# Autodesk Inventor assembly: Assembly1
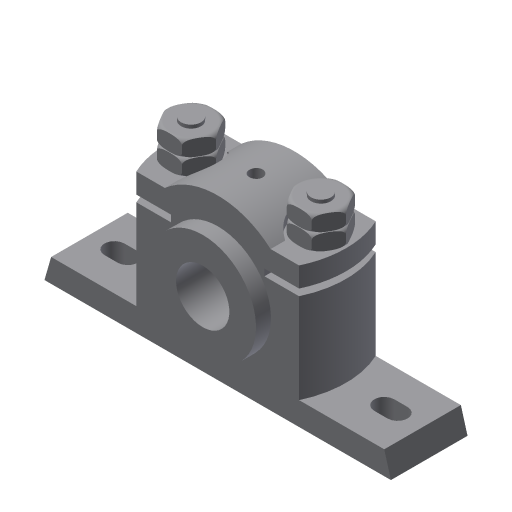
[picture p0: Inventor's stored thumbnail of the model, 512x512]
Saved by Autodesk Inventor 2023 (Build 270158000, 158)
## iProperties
Created: 2016-03
Part Number: Assembly1
Document SubType Name: Assembly
Designer: Sandeep
Author: Sandeep
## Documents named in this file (7)
- D:\PROJECTS\Project 2022\Autodesk Inventor For Professional 2023\RESOURCES INVENTOR 2023\RESOURCES INVENTOR 2023\Inventor_2023_Part\Inventor_2023_Part\c13_Inv_2023_prt\fig-13-7\Plummer block assy\Assembly1.iam
- D:\PROJECTS\Project 2022\Autodesk Inventor For Professional 2023\RESOURCES INVENTOR 2023\RESOURCES INVENTOR 2023\Inventor_2023_Part\Inventor_2023_Part\c13_Inv_2023_prt\fig-13-7\Plummer block assy\Casting.ipt
- D:\PROJECTS\Project 2022\Autodesk Inventor For Professional 2023\RESOURCES INVENTOR 2023\RESOURCES INVENTOR 2023\Inventor_2023_Part\Inventor_2023_Part\c13_Inv_2023_prt\fig-13-7\Plummer block assy\Brasses.ipt
- D:\PROJECTS\Project 2022\Autodesk Inventor For Professional 2023\RESOURCES INVENTOR 2023\RESOURCES INVENTOR 2023\Inventor_2023_Part\Inventor_2023_Part\c13_Inv_2023_prt\fig-13-7\Plummer block assy\Cap.ipt
- D:\PROJECTS\Project 2022\Autodesk Inventor For Professional 2023\RESOURCES INVENTOR 2023\RESOURCES INVENTOR 2023\Inventor_2023_Part\Inventor_2023_Part\c13_Inv_2023_prt\fig-13-7\Plummer block assy\Bolt.ipt
- D:\PROJECTS\Project 2022\Autodesk Inventor For Professional 2023\RESOURCES INVENTOR 2023\RESOURCES INVENTOR 2023\Inventor_2023_Part\Inventor_2023_Part\c13_Inv_2023_prt\fig-13-7\Plummer block assy\Nut.ipt
- D:\PROJECTS\Project 2022\Autodesk Inventor For Professional 2023\RESOURCES INVENTOR 2023\RESOURCES INVENTOR 2023\Inventor_2023_Part\Inventor_2023_Part\c13_Inv_2023_prt\fig-13-7\Plummer block assy\Lock Nut.ipt
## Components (9 placed, 6 different names)
1. Casting:1 — Mate:1, Mate:2, Insert:1, Insert:2, Angle:1, Angle:2
2. Brasses:1 — Mate:1, Mate:2, Mate:3, Mate:4
3. Cap:1 — Mate:3, Mate:4, Insert:3, Insert:5
4. Bolt:1 — Insert:1, Angle:1
5. Bolt:2 — Insert:2, Angle:2
6. Nut:1 — Insert:3, Insert:4
7. Nut:2 — Insert:5, Insert:6
8. Lock Nut:1 — Insert:4
9. Lock Nut:2 — Insert:6
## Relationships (12: Insert 6, Mate 4, Angle 2)
- Mate:1: Casting:1 ↔ Brasses:1
- Mate:2: Casting:1 ↔ Brasses:1
- Mate:3: Brasses:1 ↔ Cap:1
- Mate:4: Brasses:1 ↔ Cap:1
- Insert:1: Casting:1 ↔ Bolt:1
- Insert:2: Casting:1 ↔ Bolt:2
- Angle:1: Casting:1 ↔ Bolt:1
- Angle:2: Casting:1 ↔ Bolt:2
- Insert:3: Cap:1 ↔ Nut:1
- Insert:4: Nut:1 ↔ Lock Nut:1
- Insert:5: Cap:1 ↔ Nut:2
- Insert:6: Nut:2 ↔ Lock Nut:2
